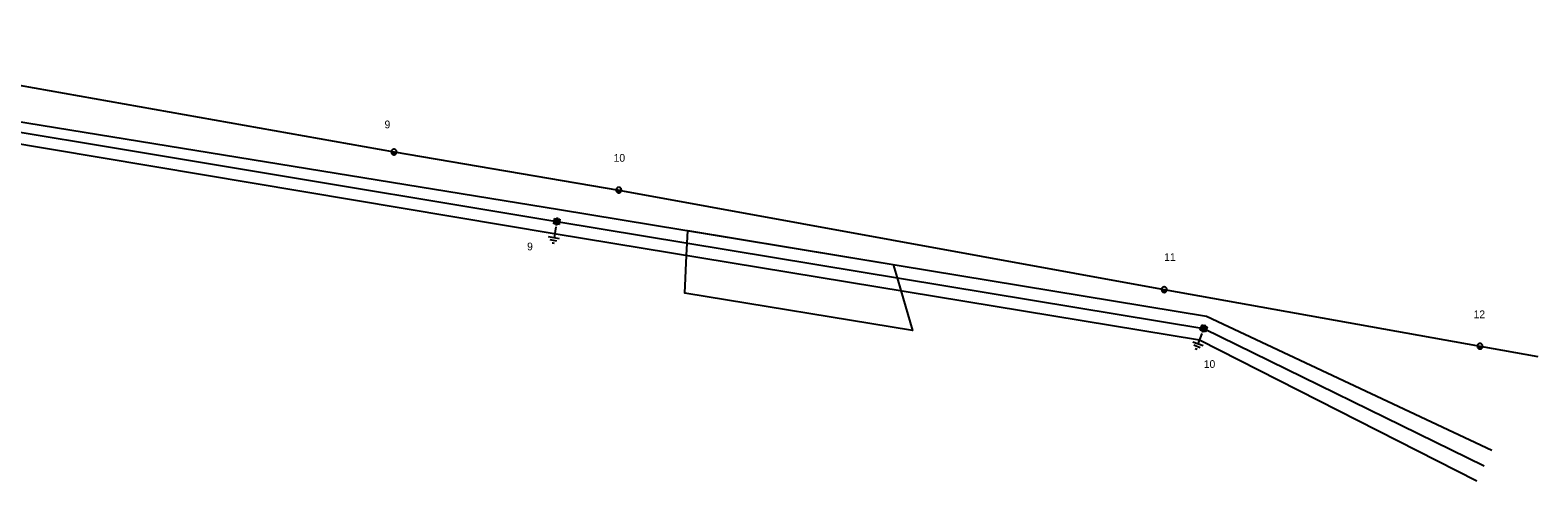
# Model space of a CAD drawing. Extents: x -717092 to -714060, y -1151159 to -1143995.
# Drawn here: x -715276.7 to -714935.4, y -1150720.1 to -1150618.1 of the extents above; entities that cross this region are included whole.
import ezdxf

# ---------------------------------------------------------------- set-up
doc = ezdxf.new("R2010")
doc.units = 0
for name, color, linetype in [('Vrstva 1', 7, 'Continuous'), ('Vrstva 13', 7, 'Continuous'), ('Vrstva 14', 7, 'Continuous'), ('Vrstva 15', 7, 'Continuous'), ('Vrstva 2', 7, 'Continuous'), ('Vrstva 35', 7, 'Continuous')]:
    doc.layers.add(name, color=color, linetype=linetype)

# ---------------------------------------------------------------- blocks, each defined once
blk = doc.blocks.new('VN440')
at = {"layer": 'Vrstva 2'}
for points in [[(1.22, 0), (1.21, 0.13), (1.19, 0.25), (1.16, 0.38), (1.11, 0.5), (1.05, 0.61), (0.98, 0.72), (0.9, 0.82), (0.81, 0.91), (0.71, 0.99), (0.6, 1.06), (0.49, 1.12), (0.37, 1.16), (0.25, 1.2), (0.12, 1.22), (-0.01, 1.22), (-0.14, 1.22), (-0.26, 1.2), (-0.39, 1.16), (-0.51, 1.12), (-0.62, 1.06), (-0.73, 0.99), (-0.83, 0.91), (-0.92, 0.82), (-1, 0.72), (-1.07, 0.61), (-1.13, 0.5), (-1.18, 0.38), (-1.21, 0.25), (-1.23, 0.13), (-1.24, 0), (-1.23, -0.13), (-1.21, -0.26), (-1.18, -0.38), (-1.13, -0.5), (-1.07, -0.62), (-1, -0.73), (-0.92, -0.83), (-0.83, -0.92), (-0.73, -1), (-0.62, -1.07), (-0.51, -1.13), (-0.39, -1.17), (-0.26, -1.2), (-0.14, -1.23), (-0.01, -1.23), (0.12, -1.23), (0.25, -1.2), (0.37, -1.17), (0.49, -1.13), (0.6, -1.07), (0.71, -1), (0.81, -0.92), (0.9, -0.83), (0.98, -0.73), (1.05, -0.62), (1.11, -0.5), (1.16, -0.38), (1.19, -0.26), (1.21, -0.13), (1.22, 0)], [(-1.24, 0), (1.22, 0)], [(-1.18, -0.34), (1.1, -0.34)], [(-1.01, -0.63), (0.97, -0.63)], [(-0.74, -0.92), (0.68, -0.92)]]:
    blk.add_lwpolyline(points, dxfattribs=at)
blk = doc.blocks.new('VN810')
at = {"layer": 'Vrstva 14'}
for points in [[(0, -1.25), (0, -3.75)], [(1.25, -3.75), (-1.25, -3.75)], [(0.77, -4.37), (-0.8, -4.37)], [(0, -5), (-0.25, -5)], [(0.27, -5), (0, -5)]]:
    blk.add_lwpolyline(points, dxfattribs=at)
blk = doc.blocks.new('VN470')
at = {"layer": 'Vrstva 2'}
for points in [[(-1.23, 1.22), (1.23, 1.22)], [(-1.23, -1.23), (-1.23, 1.22)], [(-0.92, 0.9), (0.92, 0.9)], [(-0.92, -0.95), (-0.92, 0.9)], [(-0.61, 0.61), (0.61, 0.61)], [(-0.61, -0.62), (-0.61, 0.61)], [(-0.31, -0.27), (-0.31, 0.34)], [(-0.31, 0.34), (0.31, 0.34)], [(0, 1.22), (0, 1.97)], [(0.31, 0.34), (0.31, -0.27)], [(0.61, 0.61), (0.61, -0.62)], [(0.92, 0.9), (0.92, -0.95)], [(1.23, 1.22), (1.23, -1.23)], [(1.23, -1.23), (-1.23, -1.23)], [(0.92, -0.95), (-0.92, -0.95)], [(0.61, -0.62), (-0.61, -0.62)], [(0.31, -0.27), (-0.31, -0.27)], [(0, -1.23), (0, -1.98)]]:
    blk.add_lwpolyline(points, dxfattribs=at)

msp = doc.modelspace()

# ---------------------------------------------------------------- linework, layer by layer
at = {"layer": 'Vrstva 1'}
for points in [[(-715347.92, -1150618.14), (-715289.46, -1150628.8), (-715194.36, -1150645.7), (-715143.48, -1150654.31), (-715020.02, -1150676.84), (-714948.54, -1150689.65), (-714935.45, -1150691.97)], [(-715354.01, -1150626.53), (-715305.88, -1150634.5), (-715156.87, -1150658.68), (-715010.44, -1150682.83), (-714945.86, -1150713.17)], [(-715350.08, -1150629.43), (-715306.22, -1150636.69), (-715157.5, -1150661.42), (-715011.06, -1150685.62), (-714947.58, -1150716.67)], [(-715306.18, -1150639.34), (-715158.13, -1150664.16), (-715012, -1150688.18), (-714949.27, -1150720.1)]]:
    msp.add_lwpolyline(points, dxfattribs=at)
at = {"layer": 'Vrstva 35'}
msp.add_lwpolyline([(-715081.35, -1150671.14), (-715080.47, -1150674.15), (-715079.62, -1150677.07), (-715076.99, -1150686.11), (-715128.55, -1150677.64), (-715128.13, -1150669.1), (-715128, -1150666.3), (-715127.86, -1150663.47)], close=True, dxfattribs=at)

# ---------------------------------------------------------------- block references
at = {"layer": 'Vrstva 13'}
for name, p, xscale, yscale, rotation in [('VN440', (-715194.36, -1150645.7), 0.49999999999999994, 0.49999999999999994, -9.129025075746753), ('VN440', (-715143.48, -1150654.31), 0.49999999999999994, 0.49999999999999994, -9.129025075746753), ('VN470', (-715157.5, -1150661.42), 0.5, 0.5, -9.66941110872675), ('VN440', (-715020.02, -1150676.84), 0.49999999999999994, 0.49999999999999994, -9.129025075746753), ('VN470', (-715011.06, -1150685.62), 0.5, 0.5, -20.577286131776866), ('VN440', (-714948.54, -1150689.65), 0.49999999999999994, 0.5000000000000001, -9.129024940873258)]:
    msp.add_blockref(name, p, dxfattribs=dict(at, xscale=xscale, yscale=yscale, rotation=rotation))
at = {"layer": 'Vrstva 15'}
for p, rotation in [((-715157.5, -1150661.42), -9.64176941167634), ((-715011.06, -1150685.62), -20.55071941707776)]:
    msp.add_blockref('VN810', p, dxfattribs=dict(at, rotation=rotation))

# ---------------------------------------------------------------- texts
at = {"layer": 'Vrstva 14'}
for s, p in [('9', (-715196.51, -1150640.34)), ('10', (-715144.65, -1150647.91)), ('9', (-715164.24, -1150667.95)), ('11', (-715020.02, -1150670.35)), ('12', (-714949.99, -1150683.3)), ('10', (-715011.07, -1150694.55))]:
    msp.add_text(s, height=1.75, dxfattribs=at).set_placement(p)

doc.saveas('drawing.dxf')
